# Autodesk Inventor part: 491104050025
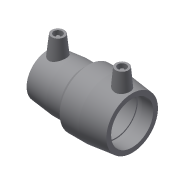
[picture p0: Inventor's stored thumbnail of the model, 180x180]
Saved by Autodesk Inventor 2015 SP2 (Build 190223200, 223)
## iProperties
Created: 2017-06
Part Number: 491104050025
Material: Generic
Description: PLASSON REDUCING COUPLER 50-25
Document SubType Name: Modeling
Designer: KIM
Mass: 54.8237 g
Surface Area: 155.252 cm^2
Volume: 54.8237 cm^3
Density: 1 g/cm^3
Appearance: Default
Author: KIM
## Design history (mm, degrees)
derived "491104.ipt"
feature "Solid1::491104.ipt"
tag "TaggingFeature1"
body "Solid1"
other parameters: "d2" = 37, "d3" = 41, "d4" = 24.6, "d5" = 33.3, "d7" = 25, "d8" = 168 deg, "d10" = 16.4, "d11" = 5.46667, "d14" = 17.6296, "d15" = 41, "d18" = 25, "d19" = 2.05, "d20" = 168 deg, "d22" = 108.92847, "d25" = 135 deg, "d29" = 41, "d30" = 15, "d31" = 35, "d34" = 6 deg, "d35" = 15, "d38" = 27.25, "d39" = 5 deg, "d41" = 4, "d42" = 14, "d43" = 0, "d45" = 4, "d46" = 14, "d47" = 0, "d48" = 37, "d50" = 68, "d52" = 22.5, "d53" = 19.6, "d54" = 6.53333, "d55" = 168 deg, "d56" = 29.4, "d57" = 49, "d58" = 61.2, "d59" = 2.05, "d60" = 135 deg, "d61" = 52, "d62" = 15, "d64" = 4, "d66" = 5 deg, "d67" = 14, "d68" = 0, "d69" = 35, "d70" = 37, "d71" = 68, "d73" = 63.92, "d76" = 2.05, "d77" = 168 deg, "d79" = 2.05, "d80" = 49, "d81" = 22.5, "d82" = 34.78, "d83" = 120 deg, "d88" = 15, "d89" = 24.5, "d90" = 5 deg, "d92" = 4, "d93" = 14, "d94" = 0, "d95" = 3, "d96" = 0, "d97" = 3, "d98" = 0, "d99" = 11.89, "d100" = 2.9725, "d101" = 33.7366, "d102" = 20 deg, "d103" = 14.21, "d104" = 3.5525, "d105" = 62.0024, "d106" = 3.60705, "d107" = 3, "d108" = 0, "d109" = 3, "d110" = 0, "d_1" = 25, "L_2" = 41, "D_1" = 37, "A_1" = 41, "d_2" = 12, "L_1" = 49, "A_" = 52, "D_" = 68
